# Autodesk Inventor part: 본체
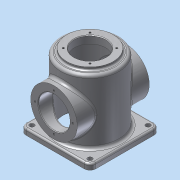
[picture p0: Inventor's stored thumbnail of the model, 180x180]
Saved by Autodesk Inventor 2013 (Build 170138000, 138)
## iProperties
Created: 2015-10
Part Number: 본체
Material: 알루미늄 6061
Document SubType Name: Modeling
Designer: Administrator
Density: 2.71 g/cm^3
Mass: 985.997 g
Surface Area: 1037.38 cm^2
Volume: 363.836 cm^3
Author: Administrator
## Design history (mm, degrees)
sketch "스케치1"
  geometry: C1 r 50 at (0, 0); 1 further point
  constraints: 1 centre point, 1 coincident
  dimensions: "d0" = 100 diameter of C1
extrude "돌출1" new body sketch "스케치1" distance "d2" = 120; taper "d3" = 0 deg
feature "쉘1" dims "d4" = 8, "d5" = 5
sketch "스케치2"
  geometry: L1 (-60, 60)-(60, 60); L2 (60, 60)-(60, -60); L3 (60, -60)-(-60, -60); L4 (-60, -60)-(-60, 60); C1 r 45 at (0, 0) reference; C2 r 50 at (0, 0) reference; 2 further points
  constraints: 8 end point, 2 midpoint, 2 parallel, 1 horizontal, 1 horizontal alignment, 1 perpendicular, 1 vertical alignment
  dimensions: "d6" = 120 distance of L1.start L1.end; "d8" = 120 distance of L1.end L2.end
extrude "돌출2" join sketch "스케치2" distance "d9" = 10; taper "d10" = 0 deg
node "작업 평면1"
sketch "스케치3"
  geometry: L1 (-60, 0)-(60, 0) reference; C1 r 40 at (0, 60); 2 further points
  constraints: 1 centre point, 1 midpoint, 1 vertical alignment
  dimensions: "d12" = 60 distance from line of C1.centre L1; "d13" = 80 diameter of C1
extrude "돌출3" join sketch "스케치3" stored distance "d14" = 10; taper "d15" = 0 deg
hole "구멍1" diameter "d18" = 54; stored, may be unused: countersink angle "d22" = 90 deg, drill point angle "d24" = 0 deg; dims "d16" = 10, "d17" = 10, "d19" = 6, "d20" = 65, "d21" = 2, "d23" = 8
sketch "스케치4"
  geometry: C1 r 27 at (0, 0) reference; 2 further points
  constraints: 1 vertical alignment
  dimensions: "d25" = 32.5 distance of C1.centre point (0, -32.5)
hole "구멍2" sketch "스케치4" at (0, -32.5) diameter "d26" = 3.242; stored, may be unused: countersink angle "d30" = 90 deg, drill point angle "d32" = 118 deg; dims "d27" = 8, "d28" = 65, "d29" = 2, "d31" = 10
sketch "스케치5"
  geometry: C1 r 50 at (0, 0) reference; C2 r 40 at (0, 0)
  constraints: 1 centre point, 1 coincident
  dimensions: "d36" = 80 diameter of C2
extrude "돌출4" join sketch "스케치5" distance "d38" = 5; taper "d39" = 0 deg
hole "구멍3" diameter "d42" = 54; stored, may be unused: countersink angle "d46" = 90 deg, drill point angle "d48" = 0 deg; dims "d40" = 10, "d41" = 10, "d43" = 8, "d44" = 65, "d45" = 2, "d47" = 10
sketch "스케치6"
  geometry: L1 (0, 40)-(0, 0); L2 (0, 0)-(22.981, 22.981); C1 r 27 at (0, 0) reference; 1 further point
  constraints: 4 end point, 2 coincident, 1 vertical, 1 vertical alignment, 1 other
  dimensions: "d50" = 45 deg angle of L2 L1; "d51" = 32.5 distance of L2.start L2.end
hole "구멍4" sketch "스케치6" at (22.981, 22.981) diameter "d53" = 3.242; stored, may be unused: countersink angle "d57" = 90 deg, drill point angle "d59" = 118 deg; dims "d54" = 8, "d55" = 65, "d56" = 2, "d58" = 10
sketch "스케치7"
  geometry: C1 r 50 at (0, 0) reference; 1 further point
  dimensions: "d64" = 50 horizontal distance of C1.centre point (50, -50); "d65" = 50 horizontal distance of C1.centre point (50, -50)
hole "구멍5" sketch "스케치7" at (50, -50) diameter "d66" = 8; stored, may be unused: countersink angle "d70" = 90 deg, drill point angle "d72" = 0 deg; dims "d67" = 8, "d68" = 65, "d69" = 2, "d71" = 10
fillet "모깎기1" dims "d63" = 10, "d79" = 5, "d80" = 3
chamfer "모따기1" distance "d81" = 1; stored, may be unused: second distance "d82" = 2, angle "d83" = 45 deg
chamfer "모따기2" distance "d84" = 3; stored, may be unused: second distance "d85" = 2, angle "d86" = 45 deg
node "작업 평면2"
sketch "스케치8" dims "d13" = 80
  geometry: L1 (-50, 0)-(50, 0) reference; 3 further points
  constraints: 1 midpoint, 1 vertical alignment, 1 other
  dimensions: "d87" = 70 distance from line of L1 point (0, 70)
feature "엠보싱1" sketch "스케치8" dims "d12" = 60, "d13" = 80, "d88" = 0.5, "d89" = 0
node "솔리드1"
pattern_circular "원형 패턴1" dims angle "d34" = 360 deg
mirror "대칭1"
pattern_circular "원형 패턴2" dims angle "d61" = 360 deg
pattern_linear "직사각형 패턴1" dims "d75" = 100
other parameters: "d11" = 62
